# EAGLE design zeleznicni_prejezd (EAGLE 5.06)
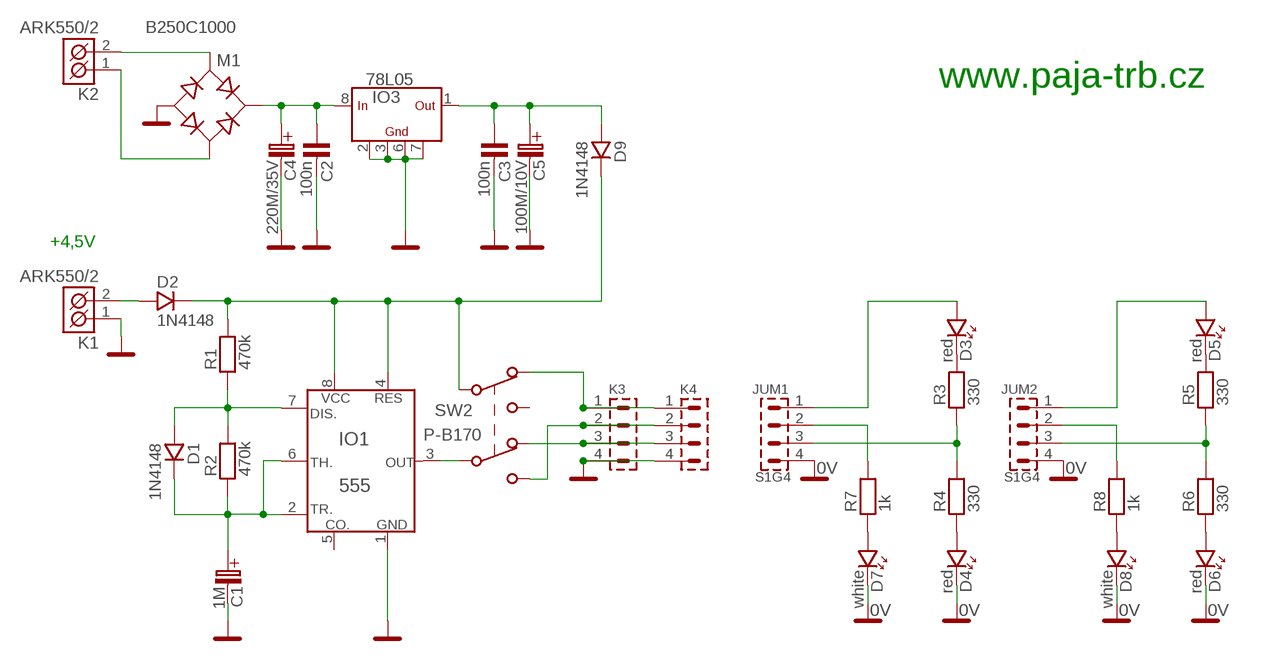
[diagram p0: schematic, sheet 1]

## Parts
C1  1M  1M/50V  [C_EL_2]
C2  100n  C-KER_1206  [1206]
C3  100n  C-KER_1206  [1206]
C4  220M/35V  [C_EL_5]
C5  100M/10V  [C_EL_2]
D1  1N4148  1N4148.  [SOD-80]
D2  1N4148  1N4148.  [SOD-80]
D3  red  LED_5  [LED_5]
D4  red  LED_5  [LED_5]
D5  red  LED_5  [LED_5]
D6  red  LED_5  [LED_5]
D7  white  LED_5  [LED_5]
D8  white  LED_5  [LED_5]
D9  1N4148  1N4148.  [SOD-80]
IO1  555  [DIL8]
IO3  78L05  78L_SO8  [SO08]
JUM1  S1G4  S1G4_JUMP  [S1G4_JUM]
JUM2  S1G4  S1G4_JUMP  [S1G4_JUM]
K1  ARK550/2  [ARK550/2]
K2  ARK550/2  [ARK550/2]
K3  PSH02-04W  [PSH02-04W]
K4  PSH02-04W  [PSH02-04W]
M1  B250C1000  D-B250C1000SMD_MUSTEK  [DM_DB1S]
R1  470k  R_1206  [1206]
R2  470k  R_1206  [1206]
R3  330  R_1206  [1206]
R4  330  R_1206  [1206]
R5  330  R_1206  [1206]
R6  330  R_1206  [1206]
R7  1k  R_1206  [1206]
R8  1k  R_1206  [1206]
SW2  P-B170  [P-B170]

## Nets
0V: D4.K D6.K D7.K D8.K JUM1.4 JUM2.4
GND: C1.C-(C_EL-) C2.2 C3.2 C4.C-(C_EL-) C5.C-(C_EL-) IO1.1(GND) IO3.2(GND) IO3.3(GND) IO3.6(GND) IO3.7(GND) K1.1(K1) K3.4 K4.4 M1.-
N$1: C1.C+(C_EL+) D1.K IO1.2(TR.) IO1.6(TH.) R2.1
N$2: D1.A IO1.7(DIS.) R1.1 R2.2
N$3: K2.2(K2) M1.AC1
N$4: D2.K D9.K IO1.4(RES) IO1.8(VCC) R1.2 SW2.3(X1)
N$5: K2.1(K1) M1.AC2
N$7: IO1.3(OUT) SW2.6(X2)
N$8: D4.A R4.1
N$9: D3.K R3.2
N$10: JUM1.3 R3.1 R4.2
N$11: K3.1 K4.1 SW2.1(S1)
N$12: D7.A R7.1
N$13: D3.A JUM1.1
N$14: K3.3 K4.3 SW2.4(S2)
N$15: D2.A K1.2(K2)
N$16: C3.1 C5.C+(C_EL+) D9.A IO3.1(OUT)
N$17: K3.2 K4.2 SW2.5(R2)
N$18: D6.A R6.1
N$19: D5.K R5.2
N$20: JUM1.2 R7.2
N$21: JUM2.3 R5.1 R6.2
N$22: D8.A R8.1
N$23: D5.A JUM2.1
N$24: JUM2.2 R8.2
N$25: C2.1 C4.C+(C_EL+) IO3.8(IN) M1.+
Unconnected: IO1.5(CO.) IO3.4 IO3.5 SW2.2(R1)

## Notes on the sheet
- www.paja-trb.cz
- +4,5V

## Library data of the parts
C1 = #PaJa_C-el_2:1M/50V
C2 C3 = #PaJa_32:C-KER: Kondenzator - keramicky
C4 = #PaJa_C-el_2:220M/35V
C5 = #PaJa_C-el_2:100M/10V
D1 D2 D9 = #PaJa_32:1N4148: Univerzalni dioda - 0,15A, 75V
D3-D8 = #PaJa_32:LED: LED - jednobarevna
IO1 = #PaJa_32:555: IO - Casovac 555
IO3 = #PaJa_32:78L_SO8: Stabilizátor SMD - 100mA ?? - napeti => 05, 08, 09, 12, 15
JUM1 JUM2 = #PaJa_konektory:S1G4_JUMP: Radove konektory - koliky - 4x
K1 K2 = #PaJa_konektory:ARK550/2: Svorkovnice - roztec 3,5mm - dvojita
K3 K4 = #PaJa_konektory:PSH02-04: Konektory se zamkem - vidlice - 4pin
M1 = #PaJa_32:D-?_MUSTEK: Diodovy mustek - Graetz
R1-R8 = #PaJa_32:R: Rezistor
SW2 = #PaJa_prepinace:P-B170: Tlacitkovy prepinac - dvojity (8 x 8mm) P-B170G - s aretaci P-B170H - bez aretace

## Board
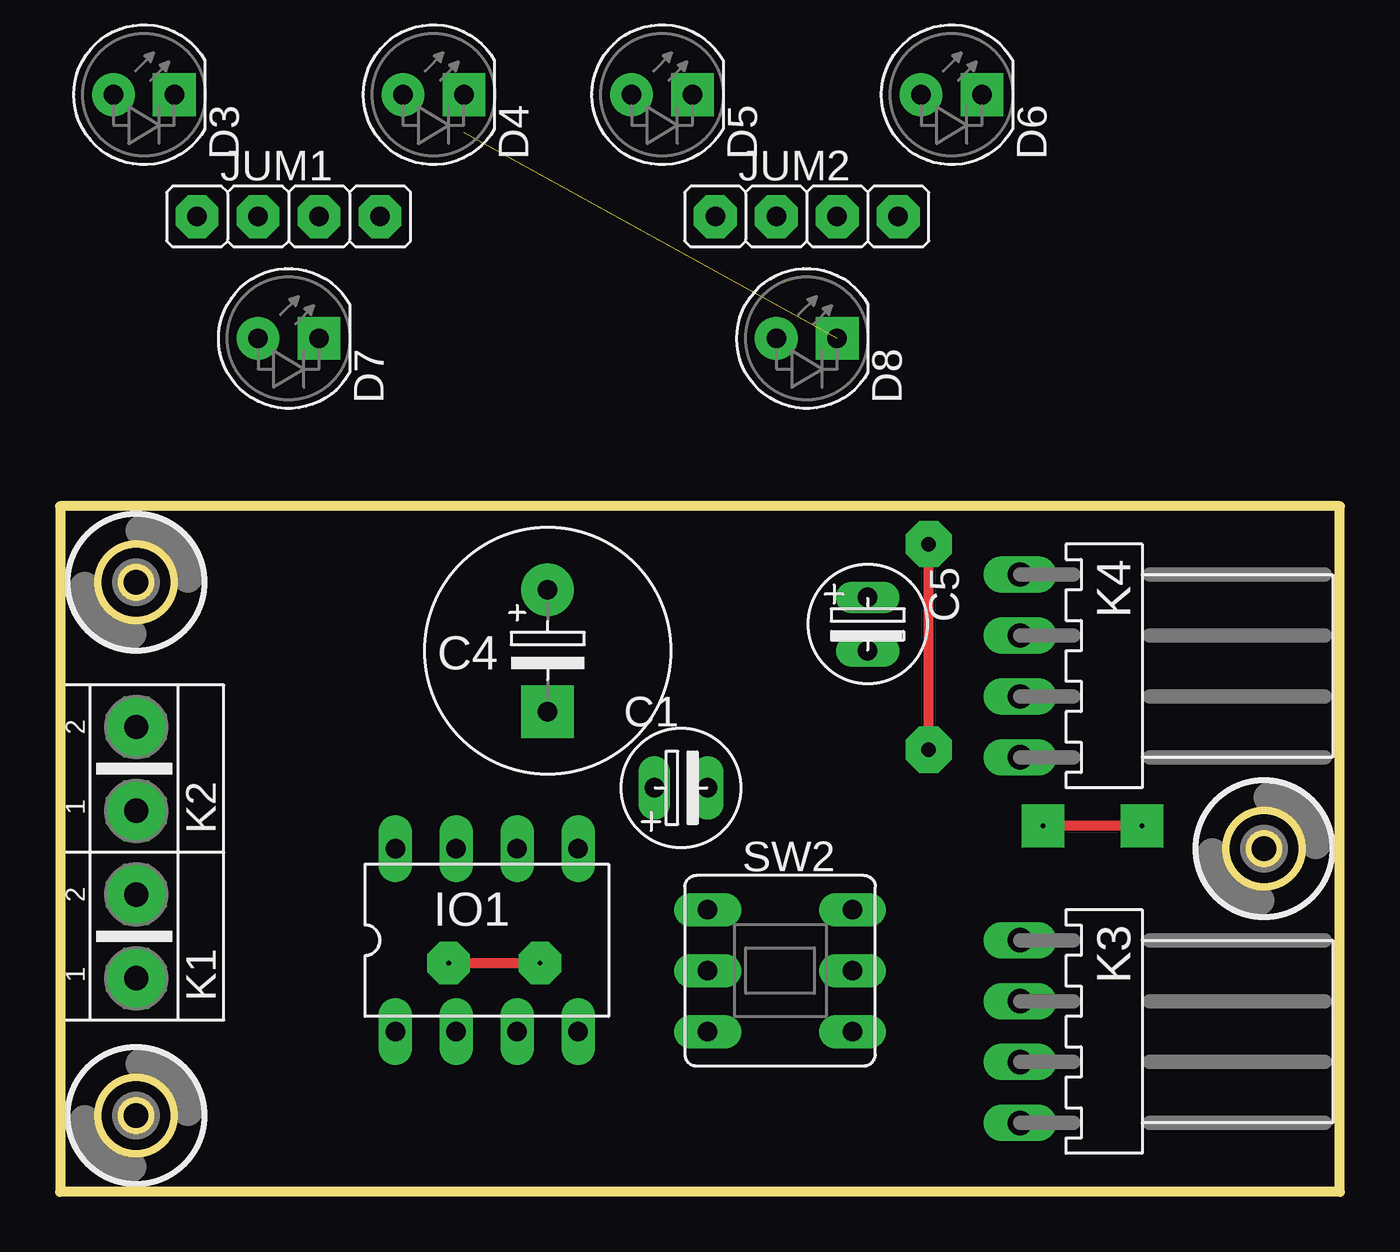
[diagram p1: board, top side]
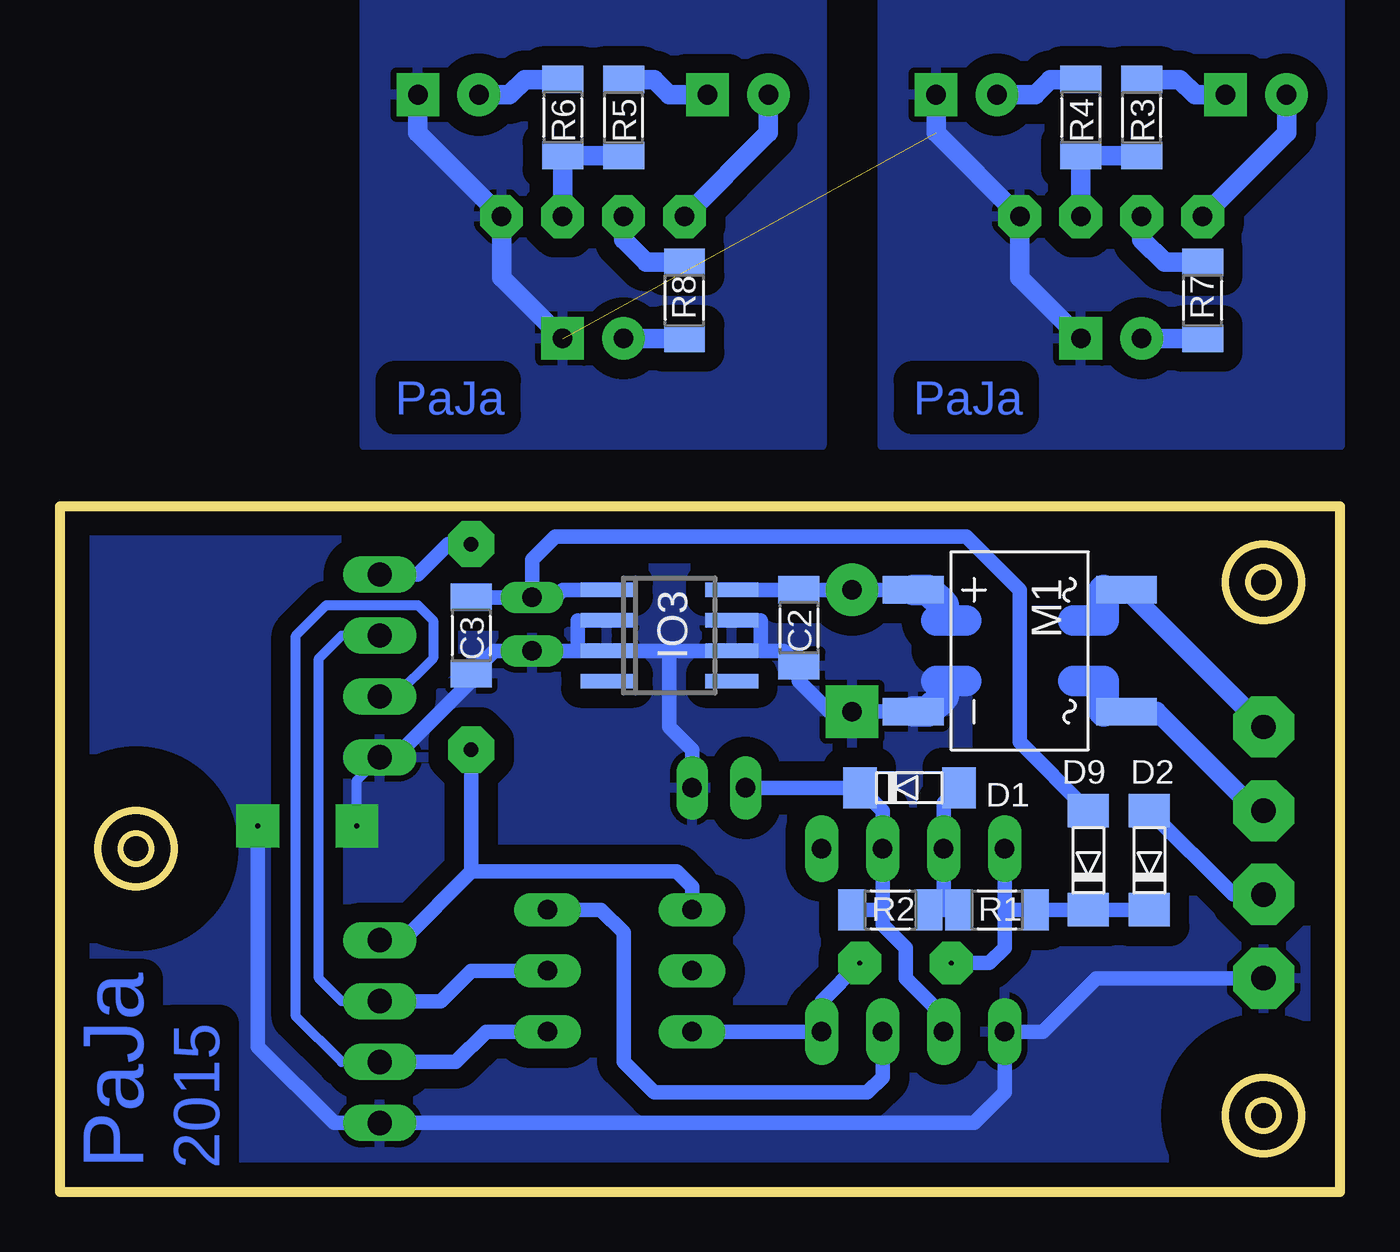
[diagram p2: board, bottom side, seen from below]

Size 53.33 x 28.58 mm. Coordinates in mm from the lower left corner, seen from the top.
Outline: 0,28.58 0,0 53.33,0 53.33,28.58 0,28.58
Copper layers (1*16): Top 0.035mm / dielectric 1.5mm / Bottom 0.035mm
Design rules "default": minimum track width 10mil, minimum drill 24mil, track to track 8mil, track to pad 8mil, pad to pad 8mil, via to via 8mil, smd to smd 8mil, copper to edge 40mil, drill to drill 8mil, minimum pad ring 10mil, minimum via ring 8mil, stop-mask expansion 4mil, vias tented up to drill 0mil, thermal gap 10mil
bRestrict: 2 lines

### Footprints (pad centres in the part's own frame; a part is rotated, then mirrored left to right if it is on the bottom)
C_EL_2 = drill 0.813 pad 1.27 long: C+ 0,0; C- 2.223,0
1206 = smd 1.143 x 1.702: 1 -1.587,0; 2 1.587,0
C_EL_5 = drill 0.813 pad 2.184 round: C+ -2.54,0 | drill 0.813 pad 2.184 square: C- 2.54,0
SOD-80 = smd 1.397 x 1.702: A 1.905,0; K -2.223,0
LED_5 = drill 0.813 pad 1.778 round: A -1.27,0 | drill 0.813 pad 1.778 square: K 1.27,0
DIL8 = drill 0.813 pad 1.4 long: 1 -3.81,-3.81; 2 -1.27,-3.81; 3 1.27,-3.81; 4 3.81,-3.81; 5 3.81,3.81; 6 1.27,3.81; 7 -1.27,3.81; 8 -3.81,3.81
SO08 = smd 0.6 x 2.2: 1 -1.905,-2.6; 2 -0.635,-2.6; 3 0.635,-2.6; 4 1.905,-2.6; 5 1.905,2.6; 6 0.635,2.6; 7 -0.635,2.6; 8 -1.905,2.6
S1G4_JUM = drill 0.813 pad 1.778 octagon: 1 -3.81,0; 2 -1.27,0; 3 1.27,0; 4 3.81,0
ARK550/2 = drill 1.016 pad 2.54 octagon: 1 0,0; 2 3.493,0
PSH02-04W = drill 1.016 pad 1.422 long: 1 -3.81,0; 2 -1.27,0; 3 1.27,0; 4 3.81,0
DM_DB1S = smd 1.146 x 2.54: + -2.54,-4.445; - 2.54,-4.445; AC1 -2.54,4.445; AC2 2.54,4.445
P-B170 = drill 0.813 pad 1.4 long: 1 0,5.08; 2 0,2.54; 3 0,0; 4 6.032,0; 5 6.032,2.54; 6 6.032,5.08
HOLE_3,0 = hole 3.2: 0,0

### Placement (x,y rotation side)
C1  24.77,16.84 0 top
C2  22.54,23.51 270 bottom
C3  36.2,23.19 270 bottom
C4  20.32,22.55 270 top
C5  33.66,24.78 270 top
D1  17.78,16.84 0 bottom
D2  7.94,13.98 90 bottom
D3  3.49,45.73 0 top  (outside the outline)
D4  15.56,45.73 0 top  (outside the outline)
D5  25.08,45.73 0 top  (outside the outline)
D6  37.15,45.73 0 top  (outside the outline)
D7  9.53,35.57 0 top  (outside the outline)
D8  31.11,35.57 0 top  (outside the outline)
D9  10.48,13.98 90 bottom
IO1  17.78,10.49 0 top
IO3  27.94,23.19 270 bottom
JUM1  9.53,40.65 0 top  (outside the outline)
JUM2  31.11,40.65 0 top  (outside the outline)
K1  3.17,8.9 90 top
K2  3.17,15.88 90 top
K3  40.01,6.68 270 top
K4  40.01,21.92 270 top
M1  13.34,22.55 270 bottom
R1  14.29,11.76 0 bottom
R2  18.73,11.76 0 bottom
R3  8.26,44.78 90 bottom  (outside the outline)
R4  10.79,44.78 270 bottom  (outside the outline)
R5  29.84,44.78 90 bottom  (outside the outline)
R6  32.38,44.78 270 bottom  (outside the outline)
R7  5.71,37.16 90 bottom  (outside the outline)
R8  27.3,37.16 90 bottom  (outside the outline)
SW2  26.99,6.68 0 top
U$1  [HOLE_3,0]  3.17,3.18 0 top
U$3  [HOLE_3,0]  50.16,14.3 0 top
U$4  [HOLE_3,0]  3.17,25.41 0 top

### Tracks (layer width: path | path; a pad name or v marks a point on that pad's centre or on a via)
0V  (1 unrouted)
  Bottom 0.813: D4.K 16.83,44.14 JUM1.4 13.34,38.11 D7.K | D8.K 34.92,38.11 JUM2.4 38.42,44.14 D6.K
  pour Bottom (isolate 0.813): 21.59,50.17 21.59,31.12 40.64,31.12 40.64,50.17
  pour Bottom (isolate 0.813): 0,50.17 0,31.12 19.05,31.12 19.05,50.17
GND  (via drill 0.2 pad 1.78)
  Top 0.406: v45.09,15.25 v40.96,15.25
  Bottom 0.406: IO3.6 24.13,22.55 | C2.2 22.54,21.28 | 31.75,23.82 IO3.2 | K4.4 40.96,17.16 v40.96,15.25
  Bottom 0.61: IO3.7 24.13,23.82 24.13,22.55 23.18,22.55 C2.2 | 22.54,21.28 21.27,20.01 C4.C- M1.- | 27.94,22.55 IO3.6 | 27.94,22.55 IO3.3 31.75,22.55 | 31.75,22.55 31.75,23.82 | 31.75,22.55 C5.C- 35.24,22.55 C3.2 36.2,21.28 39.37,18.11 K4.4 | C1.C- 26.99,18.43 27.94,19.38 27.94,22.55 | K1.1 10.16,8.9 12.38,6.68 IO1.1 13.97,4.14 15.24,2.87 K3.4 41.91,2.87 45.09,6.04 v45.09,15.25
  Bottom 1.27: 16.51,21.28 16.83,21.28 | 16.51,21.28 15.56,21.28 | 16.51,21.28 16.51,20.65 17.14,20.01 M1.-
  pour Bottom (isolate 0.813): 0,28.59 0,0.01 53.34,0.01 53.34,28.59
N$1
  Bottom 0.61: 19.05,11.76 IO1.6 19.05,15.88 D1.K C1.C+ | 19.05,11.76 R2.1 | 19.05,11.76 19.05,11.12 18.1,10.17 18.1,8.9 16.51,7.31 IO1.2
N$2
  Bottom 0.61: 16.51,11.76 IO1.7 16.51,16.2 D1.A | R2.2 16.51,11.76 | 16.51,11.76 R1.1
N$3
  Bottom 0.813: K2.2 M1.AC1
N$4  (via drill 0.2 pad 1.78)
  Top 0.406: v16.19,9.54 v20,9.54
  Bottom 0.61: D2.K D9.K R1.2 13.97,11.76 | 13.97,11.76 13.97,10.17 14.61,9.54 v16.19,9.54 | 13.97,11.76 IO1.8 | v20,9.54 21.59,7.95 IO1.4 SW2.3
N$5
  Bottom 0.406: 7.62,20.01 M1.AC2
  Bottom 0.813: K2.1 3.49,15.88 7.62,20.01
N$7
  Bottom 0.61: IO1.3 19.05,4.77 19.68,4.14 28.57,4.14 29.84,5.41 29.84,10.8 30.8,11.76 SW2.6
N$8
  Bottom 0.813: R4.1 12.06,46.36 12.7,45.73 D4.A
N$9
  Bottom 0.813: D3.K 6.03,45.73 6.67,46.36 R3.2
N$10
  Bottom 0.813: R3.1 R4.2 JUM1.3
N$11  (via drill 0.6 pad 1.93)
  Top 0.406: v36.2,18.43 v36.2,27
  Bottom 0.61: SW2.1 26.99,12.71 27.62,13.35 36.2,13.35 | 36.2,13.35 39.05,10.49 K3.1 | v36.2,27 37.15,27 38.42,25.73 K4.1 | 36.2,13.35 v36.2,18.43
N$12
  Bottom 0.813: R7.1 D7.A
N$13
  Bottom 0.813: D3.A 2.22,44.14 JUM1.1
N$14
  Bottom 0.406: K3.3 41.59,5.41 43.5,7.31 43.5,23.19 42.23,24.46 38.42,24.46 37.78,23.82 37.78,22.24 39.37,20.65 K4.3
  Bottom 0.61: SW2.4 35.56,6.68 36.83,5.41 K3.3
N$15
  Bottom 0.61: K1.2 4.45,12.39 D2.A
N$16
  Bottom 0.61: C5.C+ 32.7,24.78 32.38,25.09 IO3.1 | C5.C+ C3.1 | C5.C+ 33.66,26.36 32.7,27.32 15.56,27.32 13.34,25.09 13.34,18.74 D9.A
N$17
  Bottom 0.406: K3.2 41.59,7.95 42.55,8.9 42.55,22.24 41.59,23.19 K4.2
  Bottom 0.61: SW2.5 36.2,9.22 37.47,7.95 K3.2
N$18
  Bottom 0.813: R6.1 33.97,46.36 34.61,45.73 D6.A
N$19
  Bottom 0.813: D5.K 27.94,45.73 28.57,46.36 R5.2
N$20
  Bottom 0.813: R7.2 7.3,38.74 8.26,39.7 JUM1.2
N$21
  Bottom 0.813: R5.1 R6.2 JUM2.3
N$22
  Bottom 0.813: R8.1 D8.A
N$23
  Bottom 0.813: D5.A 23.81,44.14 JUM2.1
N$24
  Bottom 0.813: JUM2.2 29.84,39.7 28.89,38.74 R8.2
N$25
  Bottom 0.61: M1.+ C4.C+ C2.1 IO3.8
  Bottom 1.27: 16.51,23.82 15.56,23.82 | 16.51,23.82 16.83,23.82 | 16.51,23.82 16.51,24.46 17.14,25.09 M1.+
N$26
  Bottom 1.27: 11.11,21.28 9.84,21.28 9.84,20.01
N$27
  Bottom 1.27: 11.11,23.82 9.84,23.82 9.84,25.09

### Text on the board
Bottom: PaJa | PaJa | 2015 | PaJa
PaJa: www.paja-trb.cz
wago-cervena: 0R | 0R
